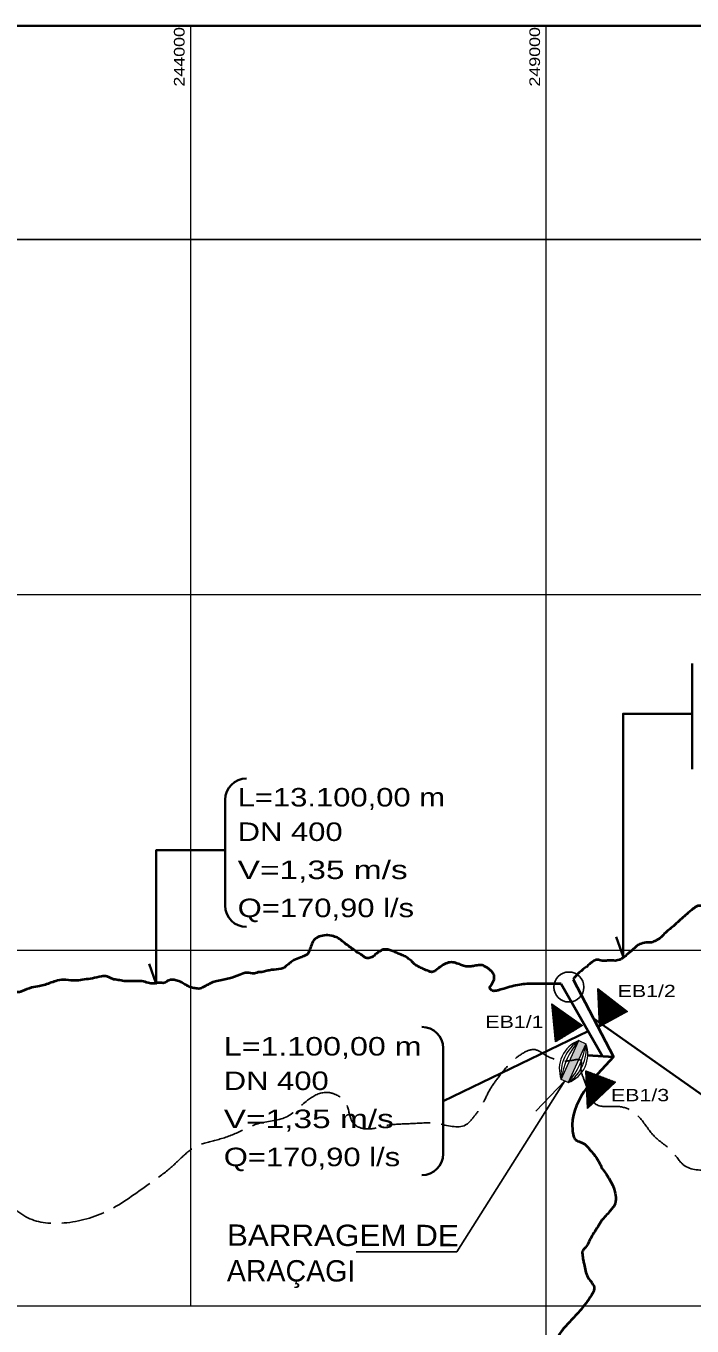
# Model space of a CAD drawing. Extents: x 0 to 1682, y 0 to 1188.
# Drawn here: x 1241.3 to 1360.7, y 551 to 783.9 of the extents above; entities that cross this region are included whole.
import ezdxf
from ezdxf.enums import TextEntityAlignment as Align

# ---------------------------------------------------------------- set-up
doc = ezdxf.new("R2010")
doc.units = 0
doc.header["$LTSCALE"] = 1.3
doc.linetypes.add('DOT_DASHED', pattern=[7.7, 5, -1.2, 0.3, -1.2])
doc.linetypes.add('LONG_DASHED', pattern=[7.5, 6, -1.5])
for name, color, linetype, lineweight in [('1', 7, 'DOT_DASHED', 13), ('4', 7, 'Continuous', 13), ('5', 7, 'LONG_DASHED', 25), ('6', 7, 'Continuous', 40), ('63', 7, 'Continuous', 25), ('8', 7, 'Continuous', 35)]:
    doc.layers.add(name, color=color, linetype=linetype, lineweight=lineweight)

msp = doc.modelspace()

# ---------------------------------------------------------------- hatches: boundary and pattern name
at = {"layer": '1'}
msp.add_hatch(color=256, dxfattribs=at).paths.add_polyline_path([(1340.46, 602.138), (1341.688, 601.576), (1338.506, 594.628), (1337.278, 595.19)])

# ---------------------------------------------------------------- linework, layer by layer
at = {"layer": '1', "linetype": 'Continuous'}
msp.add_lwpolyline([(1340.46, 602.138), (1341.688, 601.576), (1338.506, 594.628), (1337.278, 595.19)], close=True, dxfattribs=at)
for centre, radius, start, end in [((1342.303, 597.092), 5.372, 110.05739, 200.73161), ((1344.376, 596.143), 7.161, 123.14568, 187.64331), ((1350.077, 593.532), 12.906, 138.17313, 172.61588), ((1336.663, 599.675), 5.372, 290.05739, 20.73161), ((1328.889, 603.235), 12.906, 318.17313, 352.61587), ((1334.591, 600.624), 7.161, 303.14569, 7.64332)]:
    msp.add_arc(centre, radius, start, end, dxfattribs=at)
at = {"layer": '4'}
for p, q in [((1343.821, 611.366), (1343.863, 611.447)), ((1343.828, 611.208), (1343.927, 611.397)), ((1343.836, 611.05), (1343.991, 611.347)), ((1343.843, 610.892), (1344.055, 611.297)), ((1343.851, 610.734), (1344.12, 611.248)), ((1343.858, 610.576), (1344.184, 611.198)), ((1343.866, 610.418), (1344.248, 611.148)), ((1343.874, 610.26), (1344.312, 611.099)), ((1343.881, 610.102), (1344.377, 611.049)), ((1343.889, 609.945), (1344.441, 610.999)), ((1343.896, 609.787), (1344.505, 610.949)), ((1343.904, 609.629), (1344.569, 610.9)), ((1343.911, 609.471), (1344.634, 610.85)), ((1343.919, 609.313), (1344.698, 610.8)), ((1343.927, 609.155), (1344.762, 610.75)), ((1343.934, 608.997), (1344.826, 610.701)), ((1343.942, 608.839), (1344.891, 610.651)), ((1343.949, 608.681), (1344.955, 610.601)), ((1343.957, 608.523), (1345.019, 610.551)), ((1343.964, 608.365), (1345.084, 610.502)), ((1343.972, 608.207), (1345.148, 610.452)), ((1343.98, 608.049), (1345.212, 610.402)), ((1343.987, 607.891), (1345.276, 610.352)), ((1343.995, 607.733), (1345.341, 610.303)), ((1335.606, 608.655), (1335.629, 608.705)), ((1335.621, 608.498), (1335.696, 608.658)), ((1335.636, 608.34), (1335.762, 608.612)), ((1335.651, 608.183), (1335.829, 608.565)), ((1335.666, 608.025), (1335.895, 608.518)), ((1335.681, 607.868), (1335.962, 608.472)), ((1335.696, 607.711), (1336.028, 608.425)), ((1335.711, 607.553), (1336.095, 608.378)), ((1335.726, 607.396), (1336.161, 608.332)), ((1335.741, 607.238), (1336.228, 608.285)), ((1335.756, 607.081), (1336.294, 608.238)), ((1335.771, 606.923), (1336.361, 608.191)), ((1335.785, 606.766), (1336.427, 608.145)), ((1335.8, 606.608), (1336.494, 608.098)), ((1335.815, 606.451), (1336.56, 608.051)), ((1335.83, 606.293), (1336.627, 608.005)), ((1335.845, 606.136), (1336.693, 607.958)), ((1344.002, 607.575), (1345.405, 610.253)), ((1344.01, 607.417), (1345.469, 610.203)), ((1344.018, 607.259), (1345.533, 610.153)), ((1344.025, 607.101), (1345.598, 610.104)), ((1344.033, 606.943), (1345.662, 610.054)), ((1344.04, 606.785), (1345.726, 610.004)), ((1344.048, 606.627), (1345.79, 609.955)), ((1344.055, 606.469), (1345.855, 609.905)), ((1344.063, 606.311), (1345.919, 609.855)), ((1344.071, 606.153), (1345.983, 609.805)), ((1344.078, 605.995), (1346.047, 609.756)), ((1344.086, 605.837), (1346.112, 609.706)), ((1344.093, 605.679), (1346.176, 609.656)), ((1344.101, 605.521), (1346.24, 609.606)), ((1344.108, 605.363), (1346.304, 609.557)), ((1344.116, 605.205), (1346.369, 609.507)), ((1344.124, 605.047), (1346.433, 609.457)), ((1344.131, 604.889), (1346.497, 609.407)), ((1344.139, 604.731), (1346.561, 609.358)), ((1344.188, 604.653), (1346.626, 609.308)), ((1344.314, 604.722), (1346.69, 609.258)), ((1344.441, 604.791), (1346.754, 609.208)), ((1344.567, 604.86), (1346.819, 609.159)), ((1344.694, 604.929), (1346.883, 609.109)), ((1344.82, 604.998), (1346.947, 609.059)), ((1344.947, 605.067), (1347.011, 609.01)), ((1345.073, 605.136), (1347.076, 608.96)), ((1345.2, 605.205), (1347.14, 608.91)), ((1345.326, 605.275), (1347.204, 608.86)), ((1345.453, 605.344), (1347.268, 608.811)), ((1345.579, 605.413), (1347.333, 608.761)), ((1345.706, 605.482), (1347.397, 608.711)), ((1345.832, 605.551), (1347.461, 608.661)), ((1345.959, 605.62), (1347.525, 608.612)), ((1346.085, 605.689), (1347.59, 608.562)), ((1346.212, 605.758), (1347.654, 608.512)), ((1346.338, 605.827), (1347.718, 608.462)), ((1346.465, 605.896), (1347.782, 608.413)), ((1346.591, 605.966), (1347.847, 608.363)), ((1346.718, 606.035), (1347.911, 608.313)), ((1346.844, 606.104), (1347.975, 608.263)), ((1346.971, 606.173), (1348.039, 608.214)), ((1347.097, 606.242), (1348.104, 608.164)), ((1347.224, 606.311), (1348.168, 608.114)), ((1347.35, 606.38), (1348.232, 608.065)), ((1347.477, 606.449), (1348.296, 608.015)), ((1347.603, 606.518), (1348.361, 607.965)), ((1335.86, 605.979), (1336.76, 607.911)), ((1335.875, 605.821), (1336.826, 607.865)), ((1335.89, 605.664), (1336.893, 607.818)), ((1335.905, 605.506), (1336.96, 607.771)), ((1335.92, 605.349), (1337.026, 607.725)), ((1335.935, 605.191), (1337.093, 607.678)), ((1335.95, 605.034), (1337.159, 607.631)), ((1335.965, 604.876), (1337.226, 607.585)), ((1335.98, 604.719), (1337.292, 607.538)), ((1335.995, 604.561), (1337.359, 607.491)), ((1336.01, 604.404), (1337.425, 607.445)), ((1336.025, 604.247), (1337.492, 607.398)), ((1336.04, 604.089), (1337.558, 607.351)), ((1336.054, 603.932), (1337.625, 607.304)), ((1336.069, 603.774), (1337.691, 607.258)), ((1336.084, 603.617), (1337.758, 607.211)), ((1336.099, 603.459), (1337.824, 607.164)), ((1336.114, 603.302), (1337.891, 607.118)), ((1336.129, 603.144), (1337.957, 607.071)), ((1336.144, 602.987), (1338.024, 607.024)), ((1336.159, 602.83), (1338.09, 606.978)), ((1336.174, 602.672), (1338.157, 606.931)), ((1336.189, 602.515), (1338.223, 606.884)), ((1336.204, 602.357), (1338.29, 606.838)), ((1336.219, 602.2), (1338.356, 606.791)), ((1336.234, 602.042), (1338.423, 606.744)), ((1336.255, 601.898), (1338.489, 606.698)), ((1336.378, 601.973), (1338.556, 606.651)), ((1336.501, 602.048), (1338.622, 606.604)), ((1336.624, 602.123), (1338.689, 606.558)), ((1336.747, 602.198), (1338.755, 606.511)), ((1336.871, 602.273), (1338.822, 606.464)), ((1336.994, 602.347), (1338.888, 606.418)), ((1337.117, 602.422), (1338.955, 606.371)), ((1337.24, 602.497), (1339.021, 606.324)), ((1337.363, 602.572), (1339.088, 606.277)), ((1337.486, 602.647), (1339.154, 606.231)), ((1337.609, 602.722), (1339.221, 606.184)), ((1337.732, 602.797), (1339.287, 606.137)), ((1337.856, 602.872), (1339.354, 606.091)), ((1337.979, 602.947), (1339.42, 606.044)), ((1338.102, 603.022), (1339.487, 605.997)), ((1338.225, 603.097), (1339.553, 605.951)), ((1338.348, 603.172), (1339.62, 605.904)), ((1338.471, 603.247), (1339.686, 605.857)), ((1338.594, 603.322), (1339.753, 605.811)), ((1338.717, 603.397), (1339.819, 605.764)), ((1338.841, 603.472), (1339.886, 605.717)), ((1338.964, 603.546), (1339.953, 605.671)), ((1339.087, 603.621), (1340.019, 605.624)), ((1347.73, 606.588), (1348.425, 607.915)), ((1347.856, 606.657), (1348.489, 607.866)), ((1347.983, 606.726), (1348.554, 607.816)), ((1348.109, 606.795), (1348.618, 607.766)), ((1348.236, 606.864), (1348.682, 607.716)), ((1348.362, 606.933), (1348.746, 607.667)), ((1348.489, 607.002), (1348.811, 607.617)), ((1348.615, 607.071), (1348.875, 607.567)), ((1348.742, 607.14), (1348.939, 607.517)), ((1348.868, 607.209), (1349.003, 607.468)), ((1348.995, 607.279), (1349.068, 607.418)), ((1349.121, 607.348), (1349.132, 607.368)), ((1339.21, 603.696), (1340.086, 605.577)), ((1339.333, 603.771), (1340.152, 605.531)), ((1339.456, 603.846), (1340.219, 605.484)), ((1339.579, 603.921), (1340.285, 605.437)), ((1339.702, 603.996), (1340.352, 605.39)), ((1339.826, 604.071), (1340.418, 605.344)), ((1339.949, 604.146), (1340.485, 605.297)), ((1340.072, 604.221), (1340.551, 605.25)), ((1340.195, 604.296), (1340.618, 605.204)), ((1340.318, 604.371), (1340.684, 605.157)), ((1340.441, 604.446), (1340.751, 605.11)), ((1340.564, 604.521), (1340.817, 605.064)), ((1340.687, 604.596), (1340.884, 605.017)), ((1340.811, 604.67), (1340.95, 604.97)), ((1340.934, 604.745), (1341.017, 604.924)), ((1341.057, 604.82), (1341.083, 604.877)), ((1341.802, 596.67), (1341.679, 596.642)), ((1341.937, 596.619), (1341.683, 596.56)), ((1342.072, 596.568), (1341.687, 596.479)), ((1342.206, 596.517), (1341.692, 596.398)), ((1342.341, 596.466), (1341.696, 596.317)), ((1342.476, 596.415), (1341.7, 596.236)), ((1342.611, 596.364), (1341.704, 596.155)), ((1342.746, 596.313), (1341.708, 596.074)), ((1342.88, 596.262), (1341.712, 595.992)), ((1343.015, 596.211), (1341.716, 595.911)), ((1343.15, 596.16), (1341.72, 595.83)), ((1343.285, 596.109), (1341.724, 595.749)), ((1343.42, 596.058), (1341.728, 595.668)), ((1343.554, 596.007), (1341.732, 595.587)), ((1343.689, 595.956), (1341.737, 595.505)), ((1343.824, 595.905), (1341.741, 595.424)), ((1343.959, 595.854), (1341.745, 595.343)), ((1344.094, 595.803), (1341.749, 595.262)), ((1344.228, 595.752), (1341.753, 595.181)), ((1344.363, 595.701), (1341.757, 595.1)), ((1344.498, 595.65), (1341.761, 595.019)), ((1344.633, 595.599), (1341.765, 594.937)), ((1344.768, 595.548), (1341.769, 594.856)), ((1344.903, 595.496), (1341.773, 594.775)), ((1345.037, 595.445), (1341.777, 594.694)), ((1345.172, 595.394), (1341.781, 594.613)), ((1345.307, 595.343), (1341.786, 594.532)), ((1345.442, 595.292), (1341.79, 594.45)), ((1345.577, 595.241), (1341.794, 594.369)), ((1345.711, 595.19), (1341.798, 594.288)), ((1345.846, 595.139), (1341.802, 594.207)), ((1345.981, 595.088), (1341.806, 594.126)), ((1346.116, 595.037), (1341.81, 594.045)), ((1346.251, 594.986), (1341.814, 593.963)), ((1346.385, 594.935), (1341.818, 593.882)), ((1346.52, 594.884), (1341.822, 593.801)), ((1346.655, 594.833), (1341.826, 593.72)), ((1346.79, 594.782), (1341.83, 593.639)), ((1346.925, 594.731), (1341.835, 593.558)), ((1346.955, 594.656), (1341.839, 593.477)), ((1346.84, 594.548), (1341.843, 593.395)), ((1346.725, 594.439), (1341.847, 593.314)), ((1346.61, 594.33), (1341.851, 593.233)), ((1346.496, 594.222), (1341.855, 593.152)), ((1346.381, 594.113), (1341.859, 593.071)), ((1346.266, 594.005), (1341.863, 592.99)), ((1346.151, 593.896), (1341.867, 592.908)), ((1346.036, 593.787), (1341.871, 592.827)), ((1345.921, 593.679), (1341.875, 592.746)), ((1345.806, 593.57), (1341.88, 592.665)), ((1345.691, 593.462), (1341.884, 592.584)), ((1345.576, 593.353), (1341.888, 592.503)), ((1345.461, 593.244), (1341.892, 592.421)), ((1345.346, 593.136), (1341.896, 592.34)), ((1345.231, 593.027), (1341.9, 592.259)), ((1345.116, 592.919), (1341.904, 592.178)), ((1345.001, 592.81), (1341.908, 592.097)), ((1344.886, 592.701), (1341.912, 592.016)), ((1344.771, 592.593), (1341.916, 591.935)), ((1344.656, 592.484), (1341.92, 591.853)), ((1344.541, 592.375), (1341.924, 591.772)), ((1344.426, 592.267), (1341.929, 591.691)), ((1344.311, 592.158), (1341.933, 591.61)), ((1344.196, 592.05), (1341.937, 591.529)), ((1344.081, 591.941), (1341.941, 591.448)), ((1343.966, 591.832), (1341.945, 591.366)), ((1343.851, 591.724), (1341.949, 591.285)), ((1343.736, 591.615), (1341.953, 591.204)), ((1343.621, 591.507), (1341.957, 591.123)), ((1343.506, 591.398), (1341.961, 591.042)), ((1343.391, 591.289), (1341.965, 590.961)), ((1343.276, 591.181), (1341.969, 590.88)), ((1343.161, 591.072), (1341.973, 590.798)), ((1343.046, 590.964), (1341.978, 590.717)), ((1342.931, 590.855), (1341.982, 590.636)), ((1342.816, 590.746), (1341.986, 590.555)), ((1342.701, 590.638), (1341.99, 590.474)), ((1342.586, 590.529), (1341.994, 590.393)), ((1342.471, 590.421), (1341.998, 590.311)), ((1342.356, 590.312), (1342.002, 590.23)), ((1342.241, 590.203), (1342.006, 590.149)), ((1342.127, 590.095), (1342.01, 590.068))]:
    msp.add_line(p, q, dxfattribs=at)
for points in [[(1344.144, 604.628), (1343.815, 611.484), (1349.143, 607.36)], [(1336.248, 601.894), (1335.599, 608.726), (1341.114, 604.855)], [(1347.003, 594.701), (1342.014, 589.989), (1341.675, 596.718)]]:
    msp.add_lwpolyline(points, close=True, dxfattribs=at)
at = {"layer": '4', "lineweight": 25}
msp.add_ellipse((1338.644, 611.74), major_axis=(2.687, 0), ratio=0.998913, dxfattribs=at)
at = {"layer": '5'}
msp.add_spline([(1451.442, 594.713), (1449.227, 590.884), (1446.563, 586.503), (1439.805, 584.791), (1428.258, 582.64), (1424.715, 589.542), (1422.876, 591.793), (1419.796, 585.154), (1414.598, 580.202), (1404.312, 580.171), (1404.299, 584.685), (1403.863, 584.684), (1401.614, 587.216), (1401.624, 583.972), (1397.678, 583.96), (1392.022, 590.996), (1389.49, 589.296), (1391.342, 582.672), (1391.359, 576.747), (1385.724, 576.731), (1378.954, 578.967), (1364.159, 578.923), (1359.238, 579.835), (1357.131, 582.312), (1354.117, 584.835), (1351.818, 587.742), (1349.761, 589.647), (1346.944, 590.355), (1343.364, 590.822), (1342.308, 592.634), (1341.346, 595.211), (1340.816, 597.263), (1340.812, 598.553), (1338.903, 598.547), (1337.042, 598.542), (1334.463, 599.537), (1332.455, 600.534), (1330.298, 599.807), (1328.344, 598.289), (1326.087, 595.636), (1324.371, 593.15), (1323.128, 590.69), (1321.788, 588.725), (1320.118, 587.019), (1315.053, 587.269), (1310.286, 587.255), (1306.249, 586.975), (1304.718, 586.629), (1301.513, 586.439), (1299.897, 587.469), (1298.89, 590.479), (1296.89, 592.452), (1294.985, 592.846), (1291.794, 591.447), (1287.927, 588.422), (1282.887, 587.238), (1279.09, 585.569), (1275.142, 584.239), (1271.683, 583.098), (1269.167, 581.131), (1266.953, 579.09), (1263.43, 576.475), (1256.037, 571.677), (1248.159, 569.455), (1241.668, 570.385), (1237.212, 575.318), (1236.458, 577.364), (1232.758, 579.601), (1231.058, 580.795), (1229.256, 582.749), (1228.74, 583.613), (1228.736, 584.911), (1228.112, 585.937), (1227.109, 586.962), (1225.892, 587.364), (1224.977, 586.469), (1223.929, 584.329), (1222.963, 582.189), (1222.482, 580.349), (1220.596, 578.531), (1218.737, 576.903), (1218.12, 575.413), (1215.736, 572.69), (1212.812, 570.647), (1210.683, 571.303), (1210.673, 574.851), (1210.097, 577.83), (1208.815, 579.955), (1206.637, 581.037), (1205.687, 582.832), (1204.596, 584.248)], degree=3, dxfattribs=at)
at = {"layer": '6'}
for p, q in [((1339.387, 613.081), (1346.649, 599.241)), ((1337.248, 612.307), (1344.703, 599.361)), ((1342.034, 599.525), (1346.649, 599.241))]:
    msp.add_line(p, q, dxfattribs=at)
for points in [[(1363.61, 626.032), (1362.369, 626.278), (1361.74, 626.276), (1360.879, 625.721), (1359.779, 624.808), (1358.835, 623.972), (1358.147, 623.335), (1357.138, 622.448), (1356.345, 621.801), (1355.564, 621.053), (1354.958, 620.478), (1354.478, 620.172), (1353.9, 619.88), (1353.462, 619.709), (1352.798, 619.707), (1351.583, 619.49), (1350.845, 619.106), (1350.249, 618.568), (1349.216, 617.676), (1348.307, 616.92), (1347.698, 616.613), (1347.187, 616.464), (1346.652, 616.462), (1346.055, 616.46), (1345.371, 616.458), (1344.602, 616.456), (1343.71, 616.625), (1342.903, 616.273), (1341.785, 615.319)], [(1337.248, 612.307), (1337.172, 612.307), (1334.793, 612.3), (1331.088, 612.288), (1329.816, 612.149), (1328.409, 611.847), (1326.962, 611.42), (1325.981, 611.14), (1325.368, 611.025), (1325.079, 611.024), (1324.792, 611.171), (1324.584, 611.361), (1324.5, 611.497), (1324.459, 611.613), (1324.504, 611.778), (1324.766, 612.15), (1325.02, 612.589), (1325.23, 613.088), (1325.227, 613.868), (1324.848, 614.497), (1324.385, 614.908), (1323.952, 615.22), (1323.459, 615.5), (1322.702, 615.676), (1321.721, 615.517), (1320.916, 615.415), (1320.175, 615.413), (1319.778, 615.517), (1319.045, 615.81), (1318.584, 615.979), (1317.585, 616.17), (1316.593, 615.947), (1315.619, 615.375), (1314.762, 614.708), (1314.069, 614.427), (1313.541, 614.58), (1312.497, 614.986), (1311.651, 615.423), (1310.977, 615.837), (1310.581, 616.27), (1309.927, 616.817), (1309.149, 617.282), (1308.322, 617.637), (1307.62, 617.911), (1306.903, 618.237), (1306.176, 618.434), (1305.366, 618.432), (1304.81, 618.151), (1304.292, 617.83), (1303.735, 617.353), (1303.352, 617.087), (1302.985, 616.963), (1302.271, 616.961), (1301.772, 617.287), (1300.991, 617.775), (1299.96, 618.511), (1299.135, 619.106), (1298.266, 619.771), (1297.321, 620.48), (1296.468, 620.822), (1295.114, 621.005), (1293.903, 620.769), (1292.907, 620.108), (1292.503, 619.255), (1292.133, 618.305), (1291.931, 617.783), (1291.816, 617.646), (1291.351, 617.37), (1290.549, 617.008), (1289.363, 616.53), (1288.663, 616.065), (1287.981, 615.519), (1287.457, 615.119), (1287.048, 614.989), (1285.359, 614.791), (1284.517, 614.629), (1283.622, 614.413), (1283.176, 614.411), (1282.272, 614.176), (1280.929, 614.288), (1279.644, 613.907), (1277.743, 613.28), (1276.695, 613.048), (1275.564, 612.775), (1274.614, 612.516), (1274.077, 612.218)], [(1341.799, 615.343), (1340.514, 614.332), (1339.834, 613.648), (1339.401, 613.098), (1339.387, 613.081)], [(1274.077, 612.218), (1273.439, 611.867), (1272.986, 611.633), (1272.577, 611.457), (1272.037, 611.456), (1271.194, 611.599), (1270.398, 611.88), (1269.973, 612.106), (1269.258, 612.537), (1268.232, 612.934), (1266.927, 612.93), (1266.124, 612.488), (1265.234, 612.485), (1264.238, 612.357), (1263.241, 612.482), (1262.124, 612.801), (1261.514, 612.8), (1260.303, 612.796), (1258.917, 612.792), (1257.858, 612.986), (1256.832, 613.183), (1256.445, 613.364), (1255.881, 613.625), (1254.852, 613.622), (1253.238, 613.291), (1251.751, 613.059), (1250.433, 612.878), (1248.488, 613.029), (1246.976, 612.886), (1244.746, 612.13), (1243.778, 611.909), (1242.301, 611.629), (1240.652, 610.991), (1240.004, 610.802), (1239.083, 610.926), (1237.934, 611.232), (1237.05, 611.764), (1235.784, 612.221), (1234.648, 612.647), (1233.58, 613), (1232.595, 613.24), (1232.019, 613.469)], [(1346.649, 599.241), (1339.275, 586.129), (1339.478, 585.035), (1339.85, 584.373), (1340.744, 583.96), (1341.277, 583.702), (1342.694, 582.24), (1343.592, 581.153), (1344.308, 579.858), (1344.512, 579.355)], [(1344.512, 579.355), (1347.048, 574.056), (1346.78, 572.547), (1346.379, 572.04), (1345.8, 571.314), (1345.026, 570.476), (1344.171, 569.379), (1343.481, 568.211), (1342.778, 567.15), (1342.241, 566.065), (1341.62, 565.074), (1341.058, 564.26), (1341.06, 563.848), (1341.215, 562.824), (1341.371, 562.06), (1342.073, 559.724), (1343.192, 557.666), (1342.723, 556.55), (1340.533, 553.647), (1338.481, 551.412), (1337.178, 549.876), (1335.96, 547.505), (1335.047, 545.719), (1334.076, 544.769), (1333.746, 543.487), (1332.919, 540.922), (1331.505, 539.274), (1330.343, 537.913), (1329.279, 537.109), (1327.927, 536.694), (1327.478, 535.851), (1327.134, 534.536), (1326.933, 533.119), (1326.937, 531.771), (1326.511, 530.038), (1326.249, 528.518), (1326.254, 526.896), (1326.258, 525.549), (1326.262, 524.201), (1326.838, 523.572), (1327.067, 522.587), (1327.069, 521.684), (1326.754, 520.698), (1326.278, 519.543), (1325.997, 517.931), (1325.534, 516.421), (1325.217, 515.461), (1325.014, 514.866), (1325.289, 514.238), (1325.921, 513.075), (1325.921, 512.869), (1326.516, 512.265), (1326.918, 511.649), (1327.456, 511.011), (1327.907, 510.369), (1328.43, 509.539), (1328.83, 508.733), (1329.041, 508.411), (1329.785, 508.587), (1330.279, 508.961), (1331.171, 509.386), (1331.975, 509.884), (1332.742, 510.482), (1333.484, 511.167), (1334.338, 511.592), (1334.71, 511.593), (1335.357, 511.979), (1336.869, 512.473), (1338.208, 512.745), (1339.499, 513.215), (1340.255, 513.392), (1341.106, 513.127), (1341.91, 512.908)]]:
    msp.add_spline(points, degree=3, dxfattribs=at)
at = {"layer": '63', "lineweight": 35}
msp.add_line((1640.404, 783.93), (952.314, 783.93), dxfattribs=at)
at = {"layer": '63', "lineweight": 13}
for p, q in [((1270.874, 554.567), (1270.874, 783.93)), ((1334.586, 427.142), (1334.586, 783.93)), ((1640.404, 681.991), (952.314, 681.991)), ((1640.404, 618.279), (952.314, 618.279)), ((1640.404, 554.567), (952.314, 554.567))]:
    msp.add_line(p, q, dxfattribs=at)
at = {"layer": '63'}
msp.add_line((1640.404, 745.703), (952.314, 745.703), dxfattribs=at)
at = {"layer": '8'}
for p, q in [((1360.717, 650.748), (1360.717, 669.704)), ((1277.03, 626.318), (1277.03, 645.274)), ((1368.867, 587.935), (1343.018, 606.161)), ((1316.123, 591.304), (1342.122, 603.844)), ((1316.123, 581.837), (1316.123, 600.772))]:
    msp.add_line(p, q, dxfattribs=at)
for points in [[(1360.717, 660.705), (1348.368, 660.705), (1348.368, 617.18), (1347.101, 620.746)], [(1277.03, 636.275), (1264.68, 636.275), (1264.68, 612.314), (1263.414, 615.88)]]:
    msp.add_lwpolyline(points, dxfattribs=at)
at = {"layer": '8', "lineweight": 25}
msp.add_lwpolyline([(1300.542, 564.293), (1318.548, 564.293), (1337.892, 594.909), (1332.704, 589.514)], dxfattribs=at)
at = {"layer": '8'}
for centre, start, end in [((1280.852, 645.274), 90, 180), ((1280.852, 645.274), 90, 180), ((1280.852, 645.274), 90, 180), ((1280.852, 626.318), 180, 270)]:
    msp.add_arc(centre, 3.823, start, end, dxfattribs=at)
for centre, start_param, end_param in [((1312.301, 600.772), 6.2831853, 7.8539816), ((1312.301, 600.772), 6.2831853, 7.8539816), ((1312.301, 600.772), 6.2831853, 7.8539816), ((1312.301, 581.837), 4.712389, 6.2831853)]:
    msp.add_ellipse(centre, major_axis=(3.823, 0), ratio=0.998913, start_param=start_param, end_param=end_param, dxfattribs=at)

# ---------------------------------------------------------------- texts
at = {"layer": '5', "width": 1.3}
for s, p in [('EB1/2', (1352.6, 609.924)), ('EB1/1', (1328.895, 604.406)), ('EB1/3', (1351.409, 591.273))]:
    msp.add_text(s, height=2.2, rotation=0.006, dxfattribs=at).set_placement(p, align=Align.CENTER)
at = {"layer": '63', "width": 1.25}
for s, p in [('244000', (1269.764, 773.077)), ('249000', (1333.476, 773.077))]:
    msp.add_text(s, height=1.911, rotation=90, dxfattribs=at).set_placement(p)
at = {"layer": '8'}
for s, width, p in [('L=13.100,00 m', 1.25, (1279.281, 644.082)), ('DN 400', 1.25, (1279.281, 637.903)), ('V=1,35 m/s', 1.35, (1279.281, 631.079)), ('Q=170,90 l/s', 1.25, (1279.281, 624.255)), ('L=1.100,00 m', 1.3, (1276.79, 599.459)), ('DN 400', 1.25, (1276.79, 593.279)), ('V=1,35 m/s', 1.35, (1276.79, 586.456)), ('Q=170,90 l/s', 1.25, (1276.79, 579.632))]:
    msp.add_text(s, height=3.319, dxfattribs=dict(at, width=width)).set_placement(p)
at = {"layer": '8', "width": 1.1}
msp.add_text('BARRAGEM DE ', height=3.823, rotation=359.896, dxfattribs=at).set_placement((1277.358, 565.371))
at = {"layer": '8'}
msp.add_text('ARAÇAGI', height=3.823, rotation=359.896, dxfattribs=at).set_placement((1277.347, 559))

doc.saveas('drawing.dxf')
